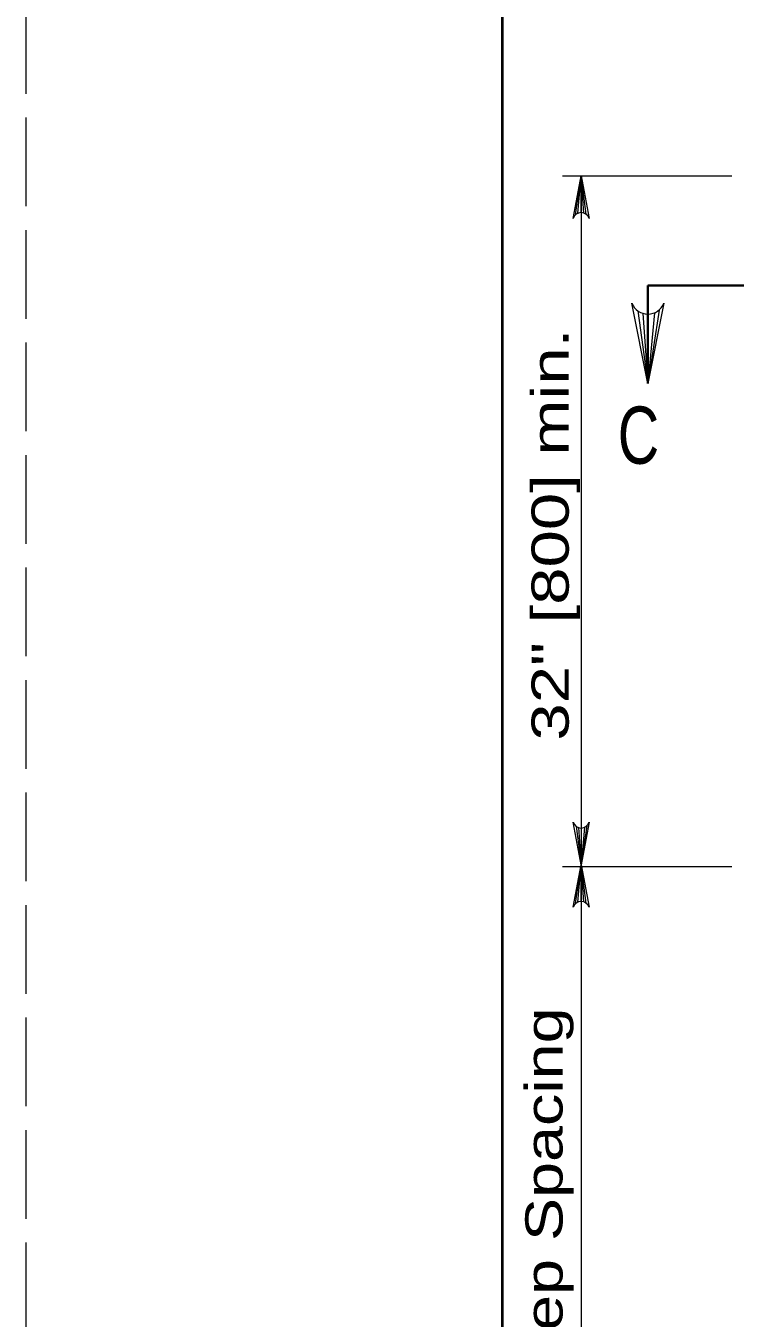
# Model space of a CAD drawing. Extents: x 1329.9 to 1363.9, y 715.5 to 737.5.
# Drawn here: x 1329.86 to 1332.84, y 728.68 to 734.11 of the extents above; entities that cross this region are included whole.
import ezdxf
from ezdxf.enums import TextEntityAlignment as Align

# ---------------------------------------------------------------- set-up
doc = ezdxf.new("R2010")
doc.units = 0
doc.header["$LTSCALE"] = 0.062
doc.linetypes.add('LONG_DASHED', pattern=[7.5, 6, -1.5])
doc.layers.add('1', color=7, linetype='Continuous', lineweight=13)

msp = doc.modelspace()

# ---------------------------------------------------------------- linework, layer by layer
at = {"layer": '1'}
for p, q in [((1332.11442, 733.47708), (1332.82617, 733.47708)), ((1332.16958, 733.31392), (1332.19317, 733.47708)), ((1332.1795, 733.32008), (1332.19317, 733.47708)), ((1332.19317, 733.32292), (1332.19317, 733.47708)), ((1332.20392, 733.32125), (1332.19317, 733.47708)), ((1332.2145, 733.31583), (1332.19317, 733.47708)), ((1332.43083, 732.91075), (1332.47342, 732.60617)), ((1332.5205, 732.91433), (1332.47342, 732.60617)), ((1332.45192, 732.9005), (1332.47342, 732.60617)), ((1332.50083, 732.90267), (1332.47342, 732.60617)), ((1332.47342, 732.89733), (1332.47342, 732.60617)), ((1332.47342, 732.86458), (1332.47342, 732.65908)), ((1332.17183, 730.74817), (1332.19317, 730.587)), ((1332.18242, 730.74275), (1332.19317, 730.587)), ((1332.21667, 730.75008), (1332.19317, 730.587)), ((1332.20683, 730.74392), (1332.19317, 730.587)), ((1332.19317, 730.74108), (1332.19317, 730.587)), ((1332.11442, 730.57925), (1332.82617, 730.57925)), ((1332.16958, 730.42383), (1332.19317, 730.587)), ((1332.1795, 730.43), (1332.19317, 730.587)), ((1332.19317, 730.43283), (1332.19317, 730.587)), ((1332.20392, 730.43117), (1332.19317, 730.587)), ((1332.2145, 730.42575), (1332.19317, 730.587))]:
    msp.add_line(p, q, dxfattribs=at)
at = {"layer": '1', "lineweight": 35}
msp.add_line((1332.47342, 733.01742), (1332.47342, 732.60617), dxfattribs=at)
at = {"layer": '1', "linetype": 'LONG_DASHED'}
msp.add_lwpolyline([(1329.86333, 715.4975), (1363.86333, 715.4975), (1363.86333, 737.4975), (1329.86333, 737.4975)], close=True, dxfattribs=at)
at = {"layer": '1', "lineweight": 25}
msp.add_lwpolyline([(1363.36333, 715.9975), (1331.86333, 715.9975), (1331.86333, 736.9975)], dxfattribs=at)
at = {"layer": '1', "lineweight": 40}
msp.add_lwpolyline([(1331.86333, 736.9975), (1363.36333, 736.9975), (1363.36333, 715.9975), (1331.86333, 715.9975)], close=True, dxfattribs=at)
msp.add_lwpolyline([(1331.86333, 736.9975), (1363.36333, 736.9975), (1363.36333, 715.9975), (1331.86333, 715.9975)], close=True, dxfattribs=at)
at = {"layer": '1'}
for points in [[(1332.1595, 733.29892), (1332.19317, 733.47708), (1332.22683, 733.29892)], [(1332.19317, 733.47708), (1332.19317, 730.587), (1332.19317, 726.14642)], [(1332.54075, 732.94267), (1332.47342, 732.60617), (1332.40617, 732.94267)], [(1332.22683, 730.76508), (1332.19317, 730.587), (1332.1595, 730.76508)], [(1332.1595, 730.40883), (1332.19317, 730.587), (1332.22683, 730.40883)]]:
    msp.add_lwpolyline(points, dxfattribs=at)
at = {"layer": '1', "lineweight": 35}
msp.add_lwpolyline([(1332.47342, 733.01742), (1338.878, 733.01742), (1338.878, 732.60617)], dxfattribs=at)
at = {"layer": '1'}
msp.add_arc((1332.47335, 732.9698), 0.07261, 202.08782, 337.91395, dxfattribs=at)
for centre, major_axis in [((1332.19315, 733.28449), (0, 0.03844)), ((1332.19315, 730.77952), (0, -0.03844)), ((1332.19315, 730.39441), (0, 0.03844))]:
    msp.add_ellipse(centre, major_axis=major_axis, ratio=0.944544, start_param=5.0978942, end_param=7.4685073, dxfattribs=at)

# ---------------------------------------------------------------- texts
for s, width, p in [('32" [800] min.', 1.35, (1332.14117, 731.10783)), ('Step Spacing', 1.3, (1332.11508, 728.37517))]:
    msp.add_text(s, height=0.156, rotation=90, dxfattribs=dict(at, width=width)).set_placement(p)
at = {"layer": '1', "width": 0.75}
msp.add_text('C', height=0.24, dxfattribs=at).set_placement((1332.43367, 732.26933), align=Align.CENTER)

doc.saveas('drawing.dxf')
